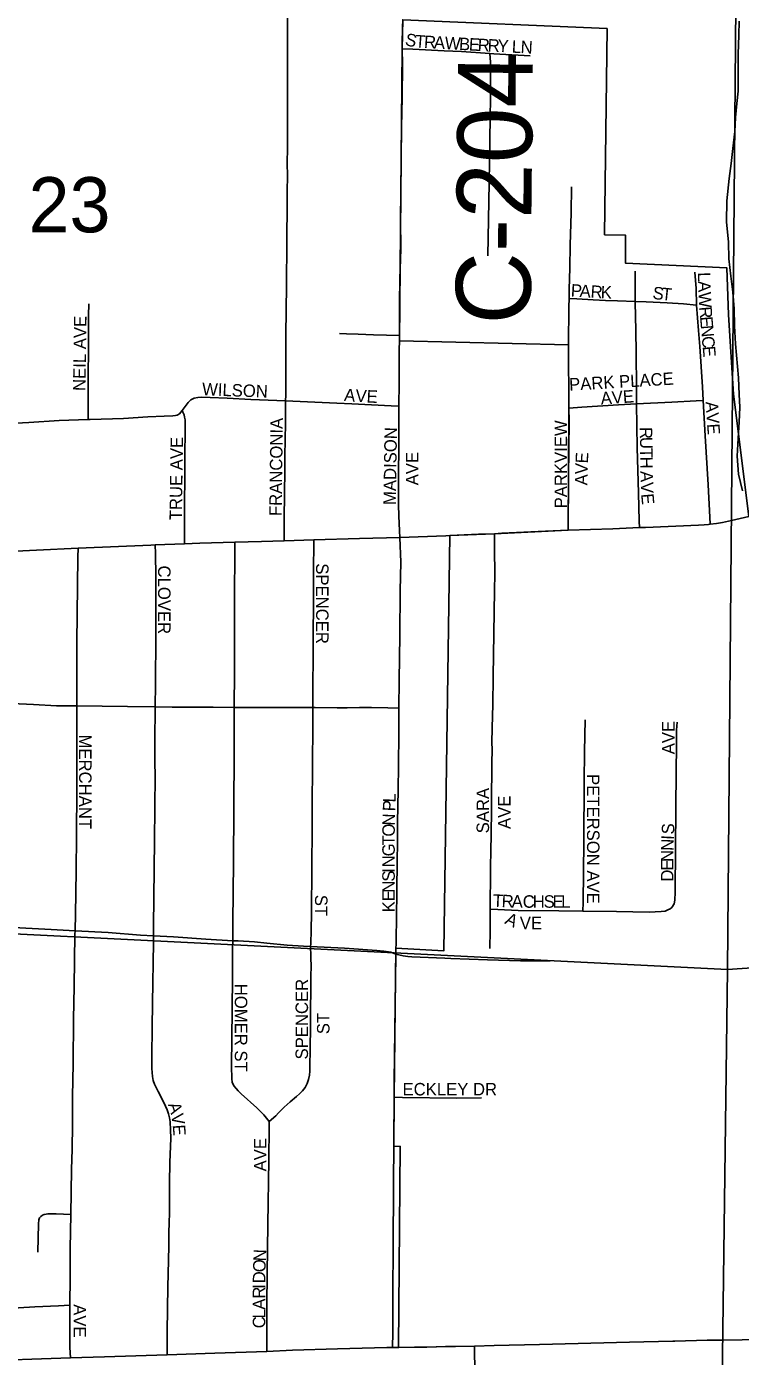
# Model space of a CAD drawing. Extents: x -97 to 34, y -21 to 22.
# Drawn here: x 7.079 to 7.621, y 19.118 to 20.128 of the extents above; entities that cross this region are included whole.
import ezdxf

# ---------------------------------------------------------------- set-up
doc = ezdxf.new("R2010")
doc.units = 0
for name, color, linetype in [('GM_X_City_Street', 7, 'Continuous'), ('GM_X_City_Street_Text', 7, 'Continuous'), ('GM_X_Corporation', 7, 'Continuous'), ('GM_X_County_Road', 7, 'Continuous'), ('GM_X_County_Road_Text', 7, 'Continuous'), ('GM_X_Minor_River', 7, 'Continuous'), ('GM_X_Section', 7, 'Continuous'), ('GM_X_Section_Text', 7, 'Continuous'), ('GM_X_State_Route', 7, 'Continuous'), ('GM_X_Township_Road', 7, 'Continuous'), ('GM_X_Township_Subdivision', 7, 'Continuous'), ('GM_X_Township_Subdivision_Text', 7, 'Continuous')]:
    doc.layers.add(name, color=color, linetype=linetype)

msp = doc.modelspace()

# ---------------------------------------------------------------- linework, layer by layer
at = {"layer": 'GM_X_City_Street'}
for points in [[(7.2755, 19.8439), (7.2756, 19.8483), (7.2756, 19.8772), (7.2757, 19.8941), (7.2762, 19.9312), (7.2764, 19.9646), (7.2767, 19.9943), (7.2767, 20.0033), (7.2768, 20.0146), (7.2767, 20.0247), (7.2768, 20.0359), (7.2769, 20.0496), (7.277, 20.082), (7.2769, 20.1093), (7.2768, 20.1184), (7.277, 20.1362), (7.2772, 20.148), (7.2773, 20.1612), (7.2775, 20.1815)], [(7.1254, 19.8297), (7.1254, 19.8338), (7.1255, 19.8394), (7.1255, 19.8458), (7.1255, 19.8541), (7.1256, 19.8667), (7.1257, 19.8795), (7.1257, 19.8909), (7.1258, 19.9005), (7.1258, 19.9087), (7.1259, 19.9175)], [(7.3164, 19.8951), (7.3217, 19.8948), (7.3306, 19.8946), (7.3423, 19.8941), (7.3619, 19.8935)], [(7.3616, 19.8398), (7.3617, 19.8577), (7.3617, 19.8695), (7.3617, 19.8785), (7.3619, 19.8935)], [(7.197, 19.8367), (7.2015, 19.8428), (7.2035, 19.8447), (7.206, 19.8459), (7.2089, 19.8465), (7.2119, 19.8467), (7.2181, 19.8465), (7.2312, 19.8459), (7.2491, 19.845), (7.2755, 19.8439)], [(7.2744, 19.7377), (7.2745, 19.745), (7.2745, 19.7509), (7.2745, 19.7544), (7.2746, 19.7733), (7.2749, 19.7912), (7.275, 19.8027), (7.2751, 19.8139), (7.2753, 19.8275), (7.2754, 19.8358), (7.2755, 19.8439)], [(7.2755, 19.8439), (7.3143, 19.8421), (7.3257, 19.8416), (7.3408, 19.841), (7.3557, 19.8401), (7.3616, 19.8398)], [(7.3622, 19.7403), (7.362, 19.7453), (7.3615, 19.7567), (7.3612, 19.7651), (7.3612, 19.7823), (7.3615, 19.8149), (7.3616, 19.8398)], [(7.0708, 19.8271), (7.0805, 19.8276), (7.1035, 19.8289), (7.1254, 19.8297)], [(7.1254, 19.8297), (7.1271, 19.8297), (7.1523, 19.8306), (7.1709, 19.8318), (7.1833, 19.8322), (7.1897, 19.8325), (7.1918, 19.8327), (7.1931, 19.833), (7.195, 19.8342), (7.196, 19.8354), (7.197, 19.8367)], [(7.1986, 19.7354), (7.1986, 19.7432), (7.1987, 19.7597), (7.1988, 19.7695), (7.1989, 19.7822), (7.1989, 19.7958), (7.199, 19.8069), (7.1991, 19.8166), (7.1991, 19.8245), (7.1991, 19.8294), (7.1988, 19.8316), (7.1983, 19.8333), (7.1975, 19.8354), (7.197, 19.8367)], [(7.2968, 19.7384), (7.2968, 19.7327), (7.2967, 19.7189), (7.2967, 19.7026), (7.2966, 19.6834), (7.2965, 19.6726), (7.2964, 19.6509), (7.2962, 19.626), (7.2962, 19.6229), (7.2962, 19.611)], [(7.3616, 19.6106), (7.3618, 19.6318), (7.3622, 19.6658), (7.3626, 19.6998), (7.363, 19.7214), (7.3622, 19.7403)], [(7.1178, 19.732), (7.1177, 19.7253), (7.1172, 19.6821), (7.1169, 19.6604), (7.1168, 19.636), (7.1169, 19.6178), (7.1169, 19.6123)], [(7.1764, 19.6116), (7.1766, 19.6288), (7.177, 19.6653), (7.1769, 19.6889), (7.177, 19.7013), (7.177, 19.7105), (7.1767, 19.728), (7.1765, 19.7345)], [(7.2365, 19.6112), (7.2366, 19.6383), (7.2367, 19.6672), (7.2367, 19.6792), (7.2367, 19.6949), (7.2368, 19.7292), (7.2368, 19.7367)], [(7.0514, 19.6148), (7.084, 19.6133), (7.1014, 19.6125), (7.115, 19.6123), (7.1169, 19.6123)], [(7.1169, 19.6123), (7.117, 19.6056), (7.117, 19.5746), (7.1168, 19.5498), (7.1166, 19.5126), (7.1163, 19.488), (7.1161, 19.4698), (7.116, 19.4545), (7.1156, 19.4416)], [(7.1169, 19.6123), (7.1553, 19.6118), (7.1764, 19.6116)], [(7.1752, 19.4378), (7.1752, 19.4389), (7.1752, 19.445), (7.1758, 19.5101), (7.1764, 19.5597), (7.1762, 19.569), (7.1762, 19.5876), (7.1764, 19.6093), (7.1764, 19.6116)], [(7.1764, 19.6116), (7.1894, 19.6115), (7.2205, 19.6114), (7.2365, 19.6112)], [(7.2354, 19.4341), (7.2355, 19.448), (7.236, 19.4936), (7.2362, 19.534), (7.2364, 19.5773), (7.2365, 19.6043), (7.2365, 19.6112)], [(7.2365, 19.6112), (7.2482, 19.611), (7.2576, 19.6111), (7.2669, 19.611), (7.2962, 19.611)], [(7.2962, 19.611), (7.2962, 19.6073), (7.2961, 19.6011), (7.2962, 19.5949), (7.2961, 19.5855), (7.296, 19.5796), (7.2958, 19.566), (7.2958, 19.557), (7.2957, 19.5463), (7.2957, 19.539), (7.2956, 19.5264), (7.2954, 19.4828), (7.2952, 19.4621), (7.2951, 19.4548), (7.2948, 19.4422), (7.2946, 19.4317), (7.2945, 19.4297)], [(7.2962, 19.611), (7.2978, 19.611), (7.3147, 19.6109), (7.3223, 19.6109), (7.3315, 19.611), (7.3407, 19.611), (7.3532, 19.6108), (7.3616, 19.6106)], [(7.3593, 19.4238), (7.3595, 19.4361), (7.3598, 19.4507), (7.3599, 19.4724), (7.3602, 19.494), (7.3604, 19.5092), (7.3604, 19.521), (7.3605, 19.5239), (7.3609, 19.5485), (7.3613, 19.5669), (7.3614, 19.5916), (7.3616, 19.6106)], [(7.0487, 19.4451), (7.054, 19.4448), (7.0974, 19.4426), (7.1156, 19.4416)], [(7.1156, 19.4416), (7.1155, 19.439), (7.1149, 19.3992), (7.1144, 19.3746), (7.1142, 19.3406), (7.1137, 19.3159), (7.1135, 19.2944), (7.1133, 19.2758), (7.1129, 19.2603), (7.1123, 19.2261)], [(7.1156, 19.4416), (7.1406, 19.4402), (7.1653, 19.4384), (7.1752, 19.4378)], [(7.1855, 19.1197), (7.1855, 19.1311), (7.1855, 19.1373), (7.186, 19.1715), (7.1862, 19.1808), (7.1867, 19.2025), (7.1869, 19.2117), (7.1871, 19.2207), (7.1872, 19.2266), (7.1874, 19.2534), (7.1875, 19.2626), (7.1876, 19.2657), (7.1883, 19.2842), (7.1881, 19.2904), (7.1878, 19.2966), (7.1872, 19.2997), (7.1864, 19.3027), (7.1854, 19.3056), (7.1829, 19.3112), (7.1786, 19.3195), (7.1759, 19.3251), (7.175, 19.328), (7.1744, 19.3309), (7.174, 19.334), (7.1739, 19.3371), (7.1738, 19.3464), (7.1742, 19.3681), (7.1744, 19.3866), (7.1751, 19.4327), (7.1752, 19.4378)], [(7.1752, 19.4378), (7.1902, 19.4369), (7.2148, 19.4352), (7.2354, 19.4341)], [(7.2362, 19.3238), (7.235, 19.3267), (7.2347, 19.3293), (7.2345, 19.3387), (7.2347, 19.3604), (7.2349, 19.3813), (7.2351, 19.4069), (7.2352, 19.4286), (7.2354, 19.4341)], [(7.2354, 19.4341), (7.2395, 19.4339), (7.2519, 19.4331), (7.2612, 19.4323), (7.2766, 19.4308), (7.2891, 19.43), (7.2945, 19.4297)], [(7.2631, 19.2969), (7.268, 19.3012), (7.2702, 19.3035), (7.2743, 19.3076), (7.2789, 19.3118), (7.2837, 19.3157), (7.2861, 19.3178), (7.2883, 19.3201), (7.2903, 19.3227), (7.2918, 19.3256), (7.2929, 19.3287), (7.2935, 19.3319), (7.2938, 19.3351), (7.2941, 19.3552), (7.2943, 19.3656), (7.2944, 19.3751), (7.2945, 19.3836), (7.2946, 19.395), (7.2947, 19.4086), (7.2948, 19.4132), (7.2947, 19.4225), (7.2945, 19.4297)], [(7.2945, 19.4297), (7.3201, 19.4283), (7.3448, 19.4266), (7.3501, 19.4261), (7.3553, 19.4253), (7.3593, 19.4238)], [(7.2362, 19.3238), (7.2378, 19.3219), (7.2395, 19.32), (7.2418, 19.3177), (7.2537, 19.3072), (7.259, 19.3018), (7.2631, 19.2969)], [(7.2612, 19.1223), (7.2612, 19.1293), (7.2612, 19.1571), (7.2615, 19.1817), (7.262, 19.2186), (7.2627, 19.2678), (7.263, 19.2926), (7.2631, 19.2969)], [(7.0874, 19.1975), (7.0877, 19.2191), (7.088, 19.2221), (7.0886, 19.2237), (7.0895, 19.2248), (7.0907, 19.2258), (7.0921, 19.2263), (7.0951, 19.2268), (7.1013, 19.2266), (7.1123, 19.2261)], [(7.1123, 19.2261), (7.1119, 19.2003), (7.1118, 19.1789), (7.1116, 19.1574)], [(7.0435, 19.1861), (7.0437, 19.1785), (7.0455, 19.1644), (7.0463, 19.1603), (7.0473, 19.1574), (7.0482, 19.1561), (7.0496, 19.1546), (7.0518, 19.1535), (7.0547, 19.1525), (7.0577, 19.1522), (7.0607, 19.1526), (7.0636, 19.1534), (7.0666, 19.1542), (7.0726, 19.1553), (7.0849, 19.1561), (7.1029, 19.1569), (7.1116, 19.1574)], [(7.1116, 19.1574), (7.1115, 19.1379), (7.1116, 19.1252), (7.1121, 19.1173)]]:
    msp.add_lwpolyline(points, dxfattribs=at)
at = {"layer": 'GM_X_Corporation'}
msp.add_lwpolyline([(7.4196, 19.0633), (7.4189, 19.1263), (7.3613, 19.1253), (7.3626, 19.2779), (7.3578, 19.2781), (7.3579, 19.3152), (7.3591, 19.4284), (7.3956, 19.4263), (7.4003, 19.7416), (7.4342, 19.7431), (7.49, 19.7457), (7.4906, 19.8385), (7.4904, 19.8865), (7.362, 19.8894), (7.3641, 20.1113), (7.3645, 20.1333), (7.5197, 20.1266), (7.5177, 19.97), (7.5336, 19.9698), (7.5336, 19.9485), (7.6107, 19.9448), (7.612, 19.9093), (7.6157, 19.849), (7.6274, 19.7561)], dxfattribs=at)
at = {"layer": 'GM_X_County_Road'}
for points in [[(7.3641, 20.1113), (7.3641, 20.1151), (7.3643, 20.1276), (7.3645, 20.1333)], [(7.3619, 19.8935), (7.3619, 19.9044), (7.362, 19.9182), (7.3623, 19.9365), (7.3629, 19.9592), (7.3628, 19.981), (7.363, 20.0029), (7.3633, 20.0277), (7.3636, 20.0519), (7.364, 20.074), (7.3642, 20.0995), (7.3641, 20.1113)], [(7.3579, 19.3152), (7.3579, 19.3273), (7.3593, 19.4238)], [(7.3567, 19.1252), (7.3569, 19.1367), (7.3569, 19.1698), (7.3571, 19.1985), (7.3575, 19.251), (7.3578, 19.2781), (7.3578, 19.2816), (7.3579, 19.3152)]]:
    msp.add_lwpolyline(points, dxfattribs=at)
at = {"layer": 'GM_X_Minor_River'}
msp.add_lwpolyline([(7.6225, 19.7755), (7.6195, 19.7884), (7.6184, 19.802), (7.6193, 19.8157), (7.6201, 19.8278), (7.6205, 19.8392), (7.6201, 19.8487), (7.6194, 19.8615), (7.6173, 19.8873), (7.6165, 19.901), (7.6162, 19.9139), (7.6151, 19.9264), (7.6137, 19.9385), (7.6122, 19.9518), (7.6119, 19.9643), (7.6104, 19.9798), (7.6105, 19.9958), (7.6124, 20.0128), (7.614, 20.0242), (7.6152, 20.0355), (7.6167, 20.0484), (7.6171, 20.059), (7.6183, 20.0696), (7.6191, 20.0791), (7.6192, 20.1071), (7.6197, 20.1215), (7.6201, 20.1322)], dxfattribs=at)
at = {"layer": 'GM_X_Section'}
for points in [[(7.6199, 20.4372), (7.611, 19.4121), (6.6081, 19.4622), (6.6105, 20.4661)], [(8.6385, 20.4574), (8.6298, 19.4815), (7.611, 19.4121), (7.6199, 20.4372)], [(8.6298, 19.4815), (8.6297, 19.4743), (8.6166, 18.456), (7.5986, 18.4548), (7.611, 19.4121)], [(6.6081, 19.4622), (7.611, 19.4121), (7.5986, 18.4548), (6.5955, 18.4662)]]:
    msp.add_lwpolyline(points, close=True, dxfattribs=at)
at = {"layer": 'GM_X_State_Route'}
for points in [[(7.49, 19.7457), (7.5241, 19.7468), (7.5442, 19.7477), (7.5488, 19.7478), (7.5891, 19.7495), (7.5934, 19.7498), (7.5966, 19.7501), (7.598, 19.7502), (7.6027, 19.7509), (7.6074, 19.7516), (7.6141, 19.753), (7.6207, 19.7545), (7.6274, 19.7561)], [(7.0706, 19.7299), (7.0862, 19.7306), (7.1178, 19.732), (7.1731, 19.7344), (7.1765, 19.7345), (7.1986, 19.7354), (7.2104, 19.7359), (7.2368, 19.7367), (7.2571, 19.7372), (7.2744, 19.7377), (7.2968, 19.7384), (7.3316, 19.7394), (7.3622, 19.7403), (7.3971, 19.7415), (7.4003, 19.7416)], [(7.4003, 19.7416), (7.4219, 19.7426), (7.4342, 19.7431), (7.4398, 19.7434), (7.4728, 19.7451), (7.49, 19.7457)], [(7.6073, 19.1309), (7.6223, 19.1311), (7.6765, 19.1321), (7.7026, 19.1326), (7.7417, 19.1332), (7.7517, 19.1333), (7.7749, 19.1336), (7.8069, 19.1339), (7.8647, 19.1342), (7.8882, 19.1343), (7.9605, 19.1354), (8.0267, 19.1368), (8.0772, 19.1374), (8.1213, 19.1384), (8.1516, 19.1391), (8.1574, 19.1392)], [(6.8924, 19.1096), (6.8994, 19.1098), (6.9781, 19.1126), (7.0387, 19.1148), (7.1121, 19.1173), (7.138, 19.1181), (7.1855, 19.1197), (7.2218, 19.1209), (7.2612, 19.1223), (7.2807, 19.1231), (7.3148, 19.1241), (7.3524, 19.1251), (7.3567, 19.1252)], [(7.3567, 19.1252), (7.3614, 19.1253), (7.3734, 19.1255), (7.3827, 19.1256), (7.3968, 19.126)], [(7.3968, 19.126), (7.3978, 19.126), (7.4028, 19.1261)], [(7.4028, 19.1261), (7.404, 19.1261), (7.4189, 19.1263)], [(7.4189, 19.1263), (7.4339, 19.1267)], [(7.4339, 19.1267), (7.4684, 19.1275), (7.5368, 19.1294), (7.5697, 19.1301), (7.5712, 19.1301)], [(7.5712, 19.1301), (7.5958, 19.1307), (7.5982, 19.1307), (7.5992, 19.1307)], [(7.5992, 19.1307), (7.6061, 19.1308), (7.6073, 19.1309)]]:
    msp.add_lwpolyline(points, dxfattribs=at)
at = {"layer": 'GM_X_Township_Road'}
for points in [[(7.3593, 19.4238), (7.3647, 19.4226), (7.3683, 19.4221), (7.3713, 19.4218), (7.3963, 19.4207)], [(7.3963, 19.4207), (7.4011, 19.4205), (7.4288, 19.4195), (7.4538, 19.4187), (7.4765, 19.4189)]]:
    msp.add_lwpolyline(points, dxfattribs=at)
at = {"layer": 'GM_X_Township_Subdivision'}
for points in [[(7.3641, 20.1113), (7.372, 20.1109), (7.3958, 20.1097), (7.409, 20.1091), (7.4307, 20.1077)], [(7.4292, 19.954), (7.4295, 19.9816), (7.4302, 20.0094), (7.4309, 20.0588), (7.4311, 20.074), (7.4312, 20.0859), (7.4311, 20.0949), (7.4311, 20.1011), (7.4307, 20.1077)], [(7.4307, 20.1077), (7.4336, 20.1075), (7.4613, 20.106)], [(7.4908, 19.9216), (7.4909, 19.9284), (7.4914, 19.9448), (7.4917, 19.9621), (7.4923, 19.9867), (7.4926, 20.0065)], [(7.5411, 19.9194), (7.5409, 19.9229), (7.5411, 19.9424)], [(7.5876, 19.9167), (7.5872, 19.9293), (7.5864, 19.9417)], [(7.4904, 19.8865), (7.4906, 19.9154), (7.4908, 19.9216)], [(7.4908, 19.9216), (7.4967, 19.9213), (7.5091, 19.9207), (7.5184, 19.9202), (7.5276, 19.9198), (7.5411, 19.9194)], [(7.5419, 19.8416), (7.5419, 19.8642), (7.5418, 19.8702), (7.5418, 19.8796), (7.5414, 19.8981), (7.5413, 19.9074), (7.5411, 19.9194)], [(7.5411, 19.9194), (7.5493, 19.9191), (7.5654, 19.9183), (7.5778, 19.9176), (7.5876, 19.9167)], [(7.5927, 19.8443), (7.5921, 19.8546), (7.59, 19.8853), (7.589, 19.8974), (7.5876, 19.9167)], [(7.4906, 19.8385), (7.4904, 19.8865)], [(7.4906, 19.8385), (7.5005, 19.8392), (7.5284, 19.8409), (7.5419, 19.8416)], [(7.5419, 19.8416), (7.5688, 19.843), (7.5873, 19.844), (7.5927, 19.8443)], [(7.5442, 19.7477), (7.5441, 19.7525), (7.5434, 19.7741), (7.5424, 19.8082), (7.5419, 19.8416)], [(7.598, 19.7502), (7.5978, 19.7557), (7.5965, 19.7803), (7.5941, 19.8175), (7.5927, 19.8443)], [(7.49, 19.7457), (7.4903, 19.7859), (7.4908, 19.8288), (7.4906, 19.8385)], [(7.4327, 19.6051), (7.4328, 19.6129), (7.4331, 19.6346), (7.4342, 19.7), (7.4343, 19.7125), (7.4342, 19.7312), (7.4342, 19.7349), (7.4342, 19.7431)], [(7.4309, 19.458), (7.4309, 19.4636), (7.4312, 19.4823), (7.4311, 19.4916), (7.4314, 19.5009), (7.4318, 19.532), (7.4319, 19.5383), (7.4322, 19.5694), (7.4323, 19.5787), (7.4322, 19.585), (7.4327, 19.6051)], [(7.5013, 19.4565), (7.5014, 19.463), (7.5019, 19.5092), (7.5023, 19.555), (7.5025, 19.5776), (7.503, 19.6017)], [(7.5689, 19.4594), (7.5705, 19.4621), (7.571, 19.4648), (7.5714, 19.4708), (7.5717, 19.5046), (7.5721, 19.5631), (7.5724, 19.5816), (7.5725, 19.5939), (7.5728, 19.6001)], [(7.4305, 19.4281), (7.4308, 19.4418), (7.4309, 19.4542), (7.4309, 19.458)], [(7.4309, 19.458), (7.4366, 19.4577), (7.452, 19.457), (7.4831, 19.4568), (7.5013, 19.4565)], [(7.5013, 19.4565), (7.5267, 19.4562), (7.5515, 19.4558), (7.5608, 19.4562), (7.5637, 19.4565), (7.5659, 19.4574), (7.5676, 19.4583), (7.5689, 19.4594)], [(7.3579, 19.3152), (7.3643, 19.3151), (7.4056, 19.3145), (7.4242, 19.3149)]]:
    msp.add_lwpolyline(points, dxfattribs=at)

# ---------------------------------------------------------------- texts
at = {"layer": 'GM_X_City_Street_Text'}
for s, rotation, p in [('NEIL AVE', 89.1065, (7.1234, 19.8514)), ('WILSON', 357.8737, (7.2119, 19.8482)), ('A', 354.3068, (7.3196, 19.844)), ('V', 356.863, (7.3284, 19.8432)), ('E', 357.2782, (7.3368, 19.8427)), ('FRANCONIA', 89.3024, (7.2725, 19.7564)), ('MADISON', 89.118, (7.3592, 19.7648)), ('TRUE AVE', 89.1777, (7.1967, 19.7532)), ('AVE', 90, (7.3763, 19.7798)), ('CLOVER', 270, (7.1786, 19.7189)), ('SPENCER', 270, (7.2986, 19.7206)), ('MERCHANT', 270, (7.1186, 19.5906)), ('P', 87.9507, (7.3587, 19.5322)), ('L', 87.983, (7.3589, 19.5389)), ('N', 88.6449, (7.3584, 19.5214)), ('O', 89.9344, (7.3584, 19.5131)), ('G', 89.9781, (7.3584, 19.4981)), ('T', 89.9956, (7.3584, 19.5064)), ('N', 90, (7.3584, 19.4898)), ('S', 89.9956, (7.3584, 19.4789)), ('I', 90, (7.3584, 19.4856)), ('N', 89.9781, (7.3584, 19.4706)), ('ST', 270, (7.2978, 19.4689)), ('E', 90, (7.3584, 19.4639)), ('K', 90, (7.3584, 19.4556)), ('HOMER ST', 270, (7.2369, 19.4014)), ('SPENCER', 90, (7.2925, 19.3439)), ('ST', 90, (7.3088, 19.3631)), ('A', 287.7921, (7.186, 19.3097)), ('V', 279.2863, (7.1884, 19.3021)), ('E', 274.1284, (7.1897, 19.2941)), ('AVE', 90, (7.2609, 19.2589)), ('N', 87.5076, (7.2604, 19.1905)), ('O', 87.8579, (7.2601, 19.1822)), ('D', 89.4972, (7.26, 19.1739)), ('I', 89.9563, (7.26, 19.1698)), ('R', 89.994, (7.26, 19.1623)), ('AVE', 270, (7.1144, 19.1581)), ('A', 89.9781, (7.26, 19.1539)), ('L', 89.9956, (7.26, 19.1473)), ('C', 89.9757, (7.26, 19.1398))]:
    msp.add_text(s, height=0.00947, rotation=rotation, dxfattribs=at).set_placement(p)
at = {"layer": 'GM_X_County_Road_Text'}
msp.add_text('C-204', height=0.05682, rotation=89.4594, dxfattribs=at).set_placement((7.4614, 19.9017))
at = {"layer": 'GM_X_Section_Text'}
msp.add_text('23', height=0.04186, rotation=0, dxfattribs=at).set_placement((7.0802, 19.9719))
at = {"layer": 'GM_X_Township_Subdivision_Text'}
for s, rotation, p in [('S', 348.2239, (7.3657, 20.114)), ('T', 355.7348, (7.3736, 20.1124)), ('R', 356.6891, (7.3804, 20.1119)), ('A', 356.784, (7.3879, 20.1115)), ('W', 356.7835, (7.3962, 20.111)), ('B', 356.7966, (7.407, 20.1104)), ('E', 356.802, (7.4145, 20.11)), ('R', 356.7932, (7.4212, 20.1096)), ('R', 357.76, (7.4288, 20.1092)), ('Y', 357.0263, (7.4363, 20.1089)), ('L', 356.993, (7.4471, 20.1083)), ('N', 356.9826, (7.4538, 20.108)), ('L', 271.9401, (7.5886, 19.9415)), ('P', 356.5276, (7.4919, 19.9232)), ('A', 356.5474, (7.4986, 19.9228)), ('R', 356.558, (7.5069, 19.9223)), ('K', 358.0675, (7.5147, 19.9218)), ('S', 352.1635, (7.5538, 19.9215)), ('T', 354.1484, (7.5607, 19.9206)), ('A', 271.9538, (7.5888, 19.9348)), ('W', 272.4661, (7.5891, 19.9264)), ('R', 274.5668, (7.5896, 19.9152)), ('E', 274.9694, (7.5902, 19.9077)), ('N', 274.9669, (7.5908, 19.901)), ('C', 274.9613, (7.5915, 19.8927)), ('E', 274.9569, (7.5922, 19.8852)), ('PARK PLACE', 3.3645, (7.4911, 19.8516)), ('AVE', 3.9434, (7.5151, 19.8411)), ('AVE', 273.9431, (7.5944, 19.8432)), ('PARKVIEW', 90, (7.4892, 19.7623)), ('R', 270.9714, (7.5444, 19.824)), ('U', 270.9953, (7.5446, 19.8165)), ('E', 87.5128, (7.5051, 19.7963)), ('T', 270.9835, (7.5447, 19.8081)), ('H', 270.9618, (7.5448, 19.8015)), ('V', 87.7697, (7.5048, 19.788)), ('A', 270.9618, (7.545, 19.7906)), ('A', 88.929, (7.5047, 19.7797)), ('V', 271.8296, (7.5452, 19.7821)), ('E', 274.9694, (7.5455, 19.7732)), ('AVE', 90, (7.5709, 19.5756)), ('PETERSON AVE', 270, (7.5044, 19.5606)), ('SARA', 90, (7.43, 19.5156)), ('AVE', 90, (7.4463, 19.5189)), ('S', 87.2672, (7.5705, 19.5146)), ('N', 88.251, (7.5701, 19.5022)), ('I', 87.3756, (7.5703, 19.5105)), ('N', 89.8907, (7.57, 19.4939)), ('E', 89.9727, (7.57, 19.4873)), ('D', 89.9781, (7.57, 19.4789)), ('T', 357.5401, (7.4327, 19.4599)), ('R', 357.5578, (7.4394, 19.4596)), ('A', 358.5516, (7.4471, 19.4593)), ('C', 359.9228, (7.4556, 19.4591)), ('H', 359.9929, (7.4632, 19.4591)), ('S', 359.9956, (7.4715, 19.4591)), ('E', 359.9956, (7.4782, 19.4591)), ('L', 359.9956, (7.4848, 19.4591)), ('A', 334.4126, (7.4414, 19.4474)), ('V', 0.2404, (7.4534, 19.4428)), ('E', 359.8361, (7.4618, 19.4428)), ('ECKLEY DR', 0, (7.3643, 19.3166))]:
    msp.add_text(s, height=0.00947, rotation=rotation, dxfattribs=at).set_placement(p)

doc.saveas('drawing.dxf')
